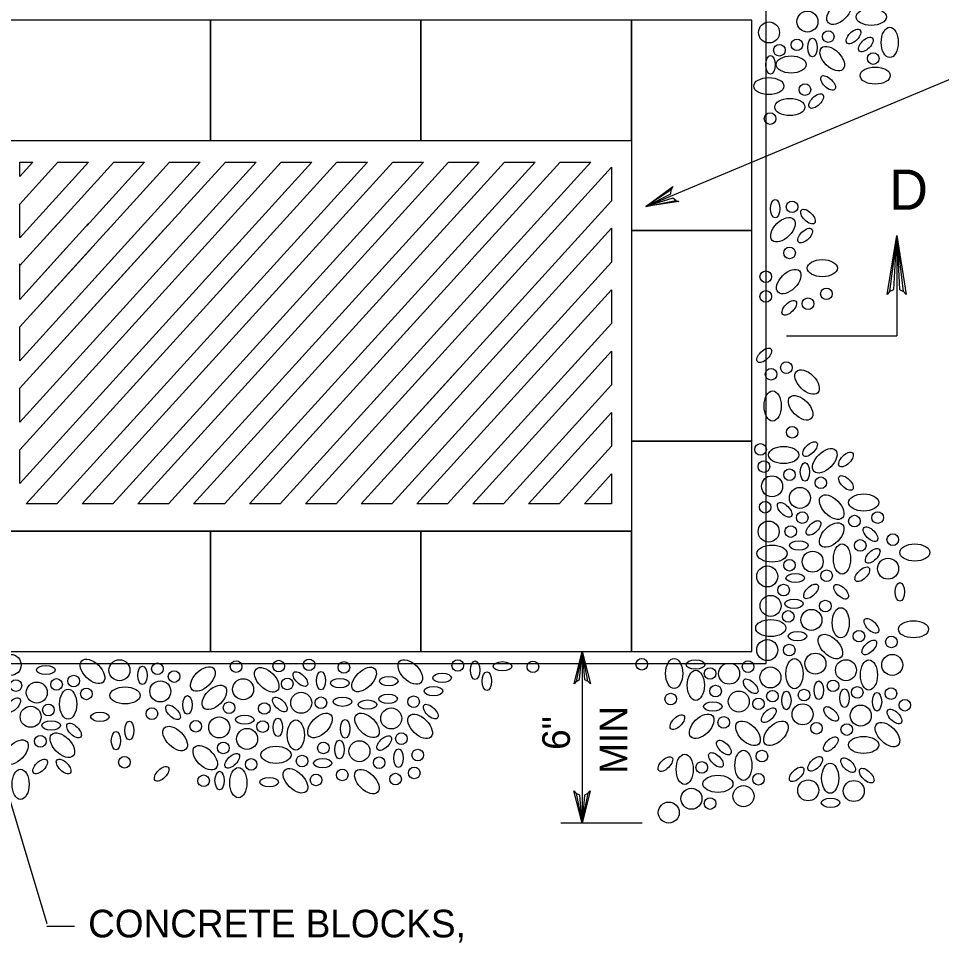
# Model space of a CAD drawing. Extents: x 636183 to 639890, y 299162 to 300538.
# Drawn here: x 637448.6 to 637548.8, y 300175.9 to 300276.1 of the extents above; entities that cross this region are included whole.
import ezdxf

# ---------------------------------------------------------------- set-up
doc = ezdxf.new("R2010")
doc.units = 0
doc.layers.add('Default', color=7, linetype='Continuous')

msp = doc.modelspace()

# ---------------------------------------------------------------- linework, layer by layer
at = {"layer": 'Default'}
for p, q in [((637516.68, 300255.74), (637562.35, 300274.87)), ((637531.92, 300241.7), (637543.9, 300241.7)), ((637446.59, 300220.51), (637515.11, 300220.51)), ((637446.59, 300220.51), (637515.11, 300220.51)), ((637440.72, 300214.38), (637451.66, 300177.93)), ((637516.28, 300188.83), (637507.46, 300188.83)), ((637454.66, 300177.6), (637451.66, 300177.6))]:
    msp.add_line(p, q, dxfattribs=at)
for points in [[(637432.27, 300206.15), (637529.74, 300206.15), (637529.74, 300277.69), (637432.27, 300277.69)], [(637469.43, 300275.96), (637446.59, 300275.96), (637446.59, 300262.88), (637469.43, 300262.88)], [(637492.27, 300275.96), (637469.43, 300275.96), (637469.43, 300262.88), (637492.27, 300262.88)], [(637515.11, 300275.96), (637492.27, 300275.96), (637492.27, 300262.88), (637515.11, 300262.88)], [(637515.11, 300275.96), (637515.11, 300253.12), (637528.18, 300253.12), (637528.18, 300275.96)], [(637515.11, 300253.12), (637515.11, 300230.28), (637528.18, 300230.28), (637528.18, 300253.12)], [(637515.11, 300230.28), (637515.11, 300207.44), (637528.18, 300207.44), (637528.18, 300230.28)], [(637469.43, 300220.51), (637446.59, 300220.51), (637446.59, 300207.44), (637469.43, 300207.44)], [(637492.27, 300220.51), (637469.43, 300220.51), (637469.43, 300207.44), (637492.27, 300207.44)], [(637515.11, 300220.51), (637492.27, 300220.51), (637492.27, 300207.44), (637515.11, 300207.44)]]:
    msp.add_lwpolyline(points, close=True, dxfattribs=at)
for points in [[(637446.59, 300220.51), (637446.59, 300262.88), (637515.11, 300262.88), (637515.11, 300220.51)], [(637446.59, 300220.51), (637446.59, 300262.88), (637515.11, 300262.88), (637515.11, 300220.51)], [(637448.73, 300229.34), (637477.1, 300260.53)], [(637448.73, 300255.97), (637452.87, 300260.53)], [(637448.73, 300225.68), (637480.43, 300260.53)], [(637448.73, 300232.34), (637474.37, 300260.53)], [(637448.73, 300252.31), (637456.2, 300260.53)], [(637448.73, 300258.97), (637450.14, 300260.53)], [(637448.73, 300258.97), (637448.73, 300260.53), (637450.14, 300260.53)], [(637448.73, 300229.34), (637477.1, 300260.53)], [(637448.73, 300255.97), (637452.87, 300260.53)], [(637448.73, 300225.68), (637480.43, 300260.53)], [(637448.73, 300232.34), (637474.37, 300260.53)], [(637448.73, 300252.31), (637456.2, 300260.53)], [(637448.73, 300258.97), (637450.14, 300260.53)], [(637448.73, 300258.97), (637448.73, 300260.53), (637450.14, 300260.53)], [(637449.44, 300223.46), (637483.15, 300260.53)], [(637449.44, 300223.46), (637483.15, 300260.53)], [(637452.52, 300253.48), (637458.93, 300260.53)], [(637452.52, 300253.48), (637458.93, 300260.53)], [(637452.77, 300223.46), (637486.48, 300260.53)], [(637452.77, 300223.46), (637486.48, 300260.53)], [(637452.87, 300260.53), (637456.2, 300260.53)], [(637452.87, 300260.53), (637456.2, 300260.53)], [(637455.49, 300223.46), (637489.21, 300260.53)], [(637455.49, 300223.46), (637489.21, 300260.53)], [(637455.99, 300253.64), (637462.26, 300260.53)], [(637455.99, 300253.64), (637462.26, 300260.53)], [(637458.21, 300253.08), (637464.98, 300260.53)], [(637458.21, 300253.08), (637464.98, 300260.53)], [(637458.82, 300223.46), (637492.54, 300260.53)], [(637458.82, 300223.46), (637492.54, 300260.53)], [(637458.93, 300260.53), (637462.26, 300260.53)], [(637458.93, 300260.53), (637462.26, 300260.53)], [(637461.55, 300223.46), (637495.26, 300260.53)], [(637461.55, 300223.46), (637495.26, 300260.53)], [(637464.72, 300256.58), (637468.31, 300260.53)], [(637464.72, 300256.58), (637468.31, 300260.53)], [(637464.88, 300223.46), (637498.59, 300260.53)], [(637464.88, 300223.46), (637498.59, 300260.53)], [(637464.98, 300260.53), (637468.31, 300260.53)], [(637464.98, 300260.53), (637468.31, 300260.53)], [(637466.15, 300255.15), (637471.04, 300260.53)], [(637466.15, 300255.15), (637471.04, 300260.53)], [(637467.6, 300223.46), (637501.32, 300260.53)], [(637467.6, 300223.46), (637501.32, 300260.53)], [(637470.94, 300223.46), (637504.65, 300260.53)], [(637470.94, 300223.46), (637504.65, 300260.53)], [(637471.04, 300260.53), (637474.37, 300260.53)], [(637471.04, 300260.53), (637474.37, 300260.53)], [(637476.99, 300223.46), (637510.71, 300260.53)], [(637476.99, 300223.46), (637510.71, 300260.53)], [(637477.1, 300260.53), (637480.43, 300260.53)], [(637477.1, 300260.53), (637480.43, 300260.53)], [(637479.72, 300223.46), (637512.96, 300260.01)], [(637479.72, 300223.46), (637512.96, 300260.01)], [(637483.15, 300260.53), (637486.48, 300260.53)], [(637483.15, 300260.53), (637486.48, 300260.53)], [(637489.21, 300260.53), (637492.54, 300260.53)], [(637489.21, 300260.53), (637492.54, 300260.53)], [(637495.26, 300260.53), (637498.59, 300260.53)], [(637495.26, 300260.53), (637498.59, 300260.53)], [(637497.44, 300249.61), (637507.38, 300260.53)], [(637497.44, 300249.61), (637507.38, 300260.53)], [(637501.32, 300260.53), (637504.65, 300260.53)], [(637501.32, 300260.53), (637504.65, 300260.53)], [(637507.38, 300260.53), (637510.71, 300260.53)], [(637507.38, 300260.53), (637510.71, 300260.53)], [(637512.96, 300260.01), (637512.96, 300256.35)], [(637512.96, 300260.01), (637512.96, 300256.35)], [(637519.92, 300256.37), (637520.25, 300256.26), (637516.68, 300255.74), (637519.92, 300256.37), (637519.6, 300256.64), (637516.68, 300255.74), (637519.4, 300257.12), (637519.42, 300257.54), (637516.68, 300255.74), (637519.59, 300257.88), (637519.42, 300257.54)], [(637448.73, 300239), (637464.76, 300256.63)], [(637448.73, 300252.31), (637448.73, 300255.97)], [(637448.73, 300252.31), (637448.73, 300255.97)], [(637502.14, 300244.45), (637512.96, 300256.35)], [(637502.14, 300244.45), (637512.96, 300256.35)], [(637448.73, 300236), (637466.32, 300255.34)], [(637448.73, 300245.65), (637456.2, 300253.87)], [(637448.73, 300249.32), (637452.74, 300253.73)], [(637448.73, 300242.66), (637458.47, 300253.36)], [(637448.73, 300236), (637464.36, 300253.19)], [(637448.73, 300239), (637461.52, 300253.06)], [(637485.77, 300223.46), (637512.96, 300253.36)], [(637485.77, 300223.46), (637512.96, 300253.36)], [(637512.96, 300253.36), (637512.96, 300249.69)], [(637512.96, 300253.36), (637512.96, 300249.69)], [(637543.13, 300246.49), (637543.57, 300246.71), (637543.9, 300252.59), (637543.13, 300246.49), (637542.86, 300246.17), (637543.9, 300252.59), (637544.19, 300246.72), (637544.62, 300246.5), (637543.9, 300252.59), (637544.92, 300246.17), (637544.62, 300246.5)], [(637543.9, 300252.59), (637543.9, 300241.7)], [(637448.73, 300249.32), (637450.51, 300251.27)], [(637448.73, 300242.66), (637456.54, 300251.25)], [(637448.73, 300245.65), (637453.74, 300251.17)], [(637473.66, 300223.46), (637497.65, 300249.83)], [(637489.1, 300223.46), (637512.96, 300249.69)], [(637489.1, 300223.46), (637512.96, 300249.69)], [(637448.73, 300245.65), (637448.73, 300249.51)], [(637448.73, 300245.65), (637448.73, 300249.51)], [(637491.83, 300223.46), (637512.96, 300246.7)], [(637491.83, 300223.46), (637512.96, 300246.7)], [(637512.96, 300246.7), (637512.96, 300243.03)], [(637512.96, 300246.7), (637512.96, 300243.03)], [(637483.05, 300223.46), (637502.26, 300244.58)], [(637448.73, 300239), (637448.73, 300242.66)], [(637448.73, 300239), (637448.73, 300242.66)], [(637473.66, 300223.46), (637491.8, 300243.4)], [(637495.16, 300223.46), (637512.96, 300243.03)], [(637495.16, 300223.46), (637512.96, 300243.03)], [(637497.89, 300223.46), (637512.96, 300240.04)], [(637497.89, 300223.46), (637512.96, 300240.04)], [(637512.96, 300240.04), (637512.96, 300236.38)], [(637512.96, 300240.04), (637512.96, 300236.38)], [(637483.05, 300223.46), (637496.34, 300238.08)], [(637448.73, 300232.34), (637448.73, 300236)], [(637448.73, 300232.34), (637448.73, 300236)], [(637501.22, 300223.46), (637512.96, 300236.38)], [(637501.22, 300223.46), (637512.96, 300236.38)], [(637503.94, 300223.46), (637512.96, 300233.38)], [(637503.94, 300223.46), (637512.96, 300233.38)], [(637512.96, 300233.38), (637512.96, 300229.72)], [(637512.96, 300233.38), (637512.96, 300229.72)], [(637507.27, 300223.46), (637512.96, 300229.72)], [(637507.27, 300223.46), (637512.96, 300229.72)], [(637448.73, 300225.68), (637448.73, 300229.34)], [(637448.73, 300225.68), (637448.73, 300229.34)], [(637510, 300223.46), (637512.96, 300226.72)], [(637512.96, 300226.72), (637512.96, 300223.46), (637510, 300223.46)], [(637510, 300223.46), (637512.96, 300226.72)], [(637512.96, 300226.72), (637512.96, 300223.46), (637510, 300223.46)], [(637452.77, 300223.46), (637449.44, 300223.46)], [(637452.77, 300223.46), (637449.44, 300223.46)], [(637458.82, 300223.46), (637455.49, 300223.46)], [(637458.82, 300223.46), (637455.49, 300223.46)], [(637464.88, 300223.46), (637461.55, 300223.46)], [(637464.88, 300223.46), (637461.55, 300223.46)], [(637470.94, 300223.46), (637467.6, 300223.46)], [(637470.94, 300223.46), (637467.6, 300223.46)], [(637476.99, 300223.46), (637473.66, 300223.46)], [(637476.99, 300223.46), (637473.66, 300223.46)], [(637483.05, 300223.46), (637479.72, 300223.46)], [(637483.05, 300223.46), (637479.72, 300223.46)], [(637489.1, 300223.46), (637485.77, 300223.46)], [(637489.1, 300223.46), (637485.77, 300223.46)], [(637495.16, 300223.46), (637491.83, 300223.46)], [(637495.16, 300223.46), (637491.83, 300223.46)], [(637501.22, 300223.46), (637497.89, 300223.46)], [(637501.22, 300223.46), (637497.89, 300223.46)], [(637507.27, 300223.46), (637503.94, 300223.46)], [(637507.27, 300223.46), (637503.94, 300223.46)], [(637509.12, 300204.2), (637508.9, 300203.93), (637509.76, 300207.44), (637509.12, 300204.2), (637509.49, 300204.4), (637509.76, 300207.44), (637510.02, 300204.41), (637510.39, 300204.22), (637509.76, 300207.44), (637510.65, 300203.94), (637510.39, 300204.22)], [(637509.76, 300207.44), (637509.76, 300188.83)], [(637510.4, 300192.07), (637510.62, 300192.34), (637509.76, 300188.83), (637510.4, 300192.07), (637510.02, 300191.87), (637509.76, 300188.83), (637509.5, 300191.86), (637509.12, 300192.05), (637509.76, 300188.83), (637508.87, 300192.33), (637509.12, 300192.05)]]:
    msp.add_lwpolyline(points, dxfattribs=at)
for centre, radius in [((637534.21, 300275.79), 1.14), ((637530.04, 300274.61), 1.14), ((637536.47, 300274.16), 0.63), ((637533.07, 300273.27), 0.63), ((637531.16, 300272.68), 0.63), ((637541.35, 300271.78), 0.63), ((637533.94, 300268.41), 0.63), ((637530.16, 300265.26), 0.63), ((637532.54, 300255.69), 0.63), ((637532.27, 300250.69), 0.63), ((637529.69, 300248.11), 0.63), ((637529.69, 300245.97), 0.63), ((637536.27, 300246.25), 0.63), ((637534.27, 300245.18), 0.63), ((637531.92, 300238.24), 0.63), ((637530.26, 300237.52), 0.63), ((637532.55, 300231.23), 0.63), ((637529.12, 300229.37), 0.63), ((637529.49, 300227.51), 0.63), ((637532.26, 300226.63), 0.63), ((637530.37, 300225.37), 1.14), ((637535.66, 300225.75), 0.63), ((637533.39, 300224.11), 1.14), ((637529.62, 300223.1), 0.63), ((637533.65, 300221.97), 0.63), ((637541.83, 300221.97), 0.63), ((637530, 300220.46), 1.14), ((637539.31, 300221.59), 0.63), ((637532.39, 300220.46), 0.63), ((637539.94, 300218.95), 0.63), ((637543.47, 300219.58), 0.63), ((637534.78, 300217.19), 1.14), ((637542.96, 300216.43), 1.14), ((637529.85, 300215.59), 1.14), ((637532.26, 300216.81), 0.63), ((637536.29, 300215.67), 0.63), ((637531.62, 300214.11), 0.63), ((637530.21, 300212.4), 1.14), ((637536.15, 300212.38), 0.63), ((637532.12, 300211.25), 0.63), ((637534.64, 300210.87), 1.14), ((637539.8, 300209.11), 0.63), ((637529.85, 300207.6), 1.14), ((637543.32, 300208.48), 0.63), ((637532.24, 300207.6), 0.63), ((637447.74, 300205.99), 1.14), ((637459.55, 300205.41), 1.14), ((637476.83, 300205.86), 0.63), ((637480.12, 300206), 0.63), ((637496.26, 300205.93), 0.63), ((637516.23, 300206.06), 0.63), ((637535.07, 300206.13), 1.14), ((637538.39, 300205.42), 1.14), ((637543.41, 300205.99), 1.14), ((637463.67, 300205.57), 0.63), ((637472.21, 300205.81), 0.63), ((637483.91, 300205.72), 0.63), ((637504.42, 300205.78), 0.63), ((637523.64, 300205.06), 0.63), ((637525.71, 300205.04), 1.14), ((637527.76, 300205.8), 0.63), ((637530.19, 300204.63), 1.14), ((637452.72, 300203.87), 0.63), ((637454.58, 300204.24), 0.63), ((637465.48, 300204.73), 0.63), ((637472.97, 300203.35), 1.14), ((637477.76, 300203.93), 0.63), ((637448.31, 300203.75), 0.63), ((637450.58, 300202.99), 1.14), ((637455.96, 300202.85), 0.63), ((637463.98, 300203.12), 1.14), ((637524.24, 300203.15), 0.63), ((637536.99, 300203.72), 0.63), ((637539.62, 300203.01), 0.63), ((637543.27, 300202.88), 0.63), ((637479.27, 300201.88), 1.14), ((637481.41, 300201.88), 0.63), ((637491.47, 300202), 0.63), ((637519.37, 300202.29), 0.63), ((637526.76, 300202.02), 1.14), ((637530.41, 300202.6), 0.63), ((637533.84, 300202.72), 0.63), ((637449.91, 300200.36), 1.14), ((637451.84, 300201.1), 0.63), ((637471.44, 300201.35), 0.63), ((637475.27, 300201.26), 0.63), ((637528.9, 300201.77), 0.63), ((637533.68, 300200.63), 1.14), ((637539.99, 300200.49), 1.14), ((637544.78, 300201.62), 0.63), ((637463.07, 300200.7), 0.63), ((637489.04, 300200.18), 1.14), ((637467.83, 300199.33), 0.63), ((637470.37, 300199.21), 1.14), ((637475.09, 300199.3), 0.63), ((637525.12, 300199.75), 0.63), ((637535.19, 300199.12), 0.63), ((637538.48, 300198.98), 0.63), ((637473.4, 300197.96), 1.14), ((637490.14, 300197.99), 0.63), ((637450.96, 300197.7), 0.63), ((637470.82, 300196.98), 0.63), ((637481.68, 300196.98), 0.63), ((637485.59, 300196.63), 1.14), ((637491.92, 300196.21), 0.63), ((637529.27, 300196.1), 0.63), ((637460.09, 300195.43), 0.63), ((637473.84, 300195.2), 0.63), ((637479.36, 300195.56), 0.63), ((637487.73, 300195.38), 0.63), ((637522.74, 300194.87), 0.63), ((637483.73, 300194.05), 0.63), ((637491.54, 300194.27), 0.63), ((637468.68, 300193.42), 0.63), ((637480.88, 300193.51), 0.63), ((637489.51, 300193.6), 0.63), ((637528.9, 300193.58), 0.63), ((637534.29, 300192.38), 1.14), ((637539.24, 300192.31), 1.14), ((637521.62, 300191.47), 1.14), ((637527.27, 300191.75), 1.14), ((637523.64, 300190.95), 0.63), ((637519.16, 300189.97), 1.14)]:
    msp.add_circle(centre, radius, dxfattribs=at)
for centre, major_axis, ratio in [((637537.65, 300276.8), (1.16, 1.16), 0.565936), ((637541.13, 300276.3), (1.64, 0), 0.565936), ((637539.21, 300274.17), (0.712, 0.712), 0.5), ((637543.14, 300273.53), (0, -1.64), 0.565936), ((637534.75, 300272.98), (0, -1.01), 0.5), ((637540.55, 300273.31), (0.712, 0.712), 0.5), ((637536.9, 300271.77), (1.16, -1.16), 0.565936), ((637530.2, 300271.1), (0, 1.01), 0.5), ((637532.44, 300271.13), (1.64, 0), 0.565936), ((637541.56, 300269.93), (1.64, 0), 0.565936), ((637530.02, 300268.79), (1.64, 0), 0.565936), ((637536.45, 300269.13), (0.712, -0.712), 0.5), ((637535.16, 300267.17), (0.712, 0.712), 0.5), ((637532.3, 300266.52), (1.64, 0), 0.565936), ((637530.71, 300255.49), (0, 1.01), 0.5), ((637531.55, 300253.21), (1.16, 1.16), 0.565936), ((637534.27, 300254.63), (0.712, -0.712), 0.5), ((637533.96, 300252.57), (0.712, 0.712), 0.5), ((637535.82, 300249.04), (1.64, 0), 0.565936), ((637532.18, 300247.58), (1.16, 1.16), 0.565936), ((637532.24, 300244.74), (0.712, 0.712), 0.5), ((637529.52, 300239.58), (0.712, 0.712), 0.5), ((637534.17, 300236.68), (1.16, -1.16), 0.565936), ((637530.43, 300234.09), (0, -1.64), 0.565936), ((637533.47, 300233.88), (1.16, -1.16), 0.565936), ((637531.63, 300228.77), (1.64, 0), 0.565936), ((637534.49, 300229.41), (0.712, 0.712), 0.5), ((637536.09, 300228.14), (1.16, 1.16), 0.565936), ((637538.39, 300228.28), (0.712, 0.712), 0.5), ((637533.94, 300226.93), (0, 1.01), 0.5), ((637538.39, 300225.73), (0.712, -0.712), 0.5), ((637536.84, 300223.11), (1.16, -1.16), 0.565936), ((637540.32, 300223.61), (1.64, 0), 0.565936), ((637531.74, 300222.81), (-0.712, 0.712), 0.5), ((637534.87, 300220.85), (0.712, 0.712), 0.5), ((637536.84, 300220.08), (1.16, 1.16), 0.565936), ((637541.06, 300220.17), (-0.712, 0.712), 0.5), ((637530.37, 300218.07), (1.64, 0), 0.565936), ((637533.27, 300218.95), (-1.01, 0), 0.5), ((637537.96, 300217.49), (0, -1.64), 0.565936), ((637541.29, 300217.83), (0.712, 0.712), 0.5), ((637545.86, 300218.19), (1.64, 0), 0.565936), ((637540.16, 300215.82), (0.712, 0.712), 0.5), ((637532.89, 300215.42), (-1.01, 0), 0.5), ((637534.6, 300213.97), (-0.712, -0.712), 0.5), ((637537.87, 300213.93), (0.712, -0.712), 0.5), ((637544.24, 300213.91), (0, 1.01), 0.5), ((637532.75, 300212.63), (-1.01, 0), 0.5), ((637537.82, 300210.56), (0, 1.64), 0.565936), ((637530.23, 300209.99), (1.64, 0), 0.565936), ((637541.15, 300210.23), (0.712, -0.712), 0.5), ((637545.72, 300209.86), (1.64, 0), 0.565936), ((637533.13, 300209.11), (-1.01, 0), 0.5), ((637536.7, 300207.98), (1.16, -1.16), 0.565936), ((637540.92, 300207.89), (-0.712, -0.712), 0.5), ((637456.62, 300205.29), (1.16, -1.16), 0.565936), ((637491.11, 300205.22), (1.16, -1.16), 0.565936), ((637519.75, 300205.06), (0, -1.64), 0.565936), ((637522.06, 300206.03), (1.01, 0), 0.5), ((637532.8, 300205.04), (0, -1.64), 0.565936), ((637540.88, 300204.9), (0, -1.64), 0.565936), ((637451.56, 300205.44), (1.01, 0), 0.5), ((637462.04, 300204.86), (0, -1.01), 0.5), ((637468.6, 300204.46), (-1.16, -1.16), 0.565936), ((637475.53, 300204.37), (1.16, -1.16), 0.565936), ((637486.1, 300204.41), (-1.16, -1.16), 0.565936), ((637498.14, 300205.41), (0, -1.01), 0.5), ((637501.12, 300205.84), (-1.01, 0), 0.5), ((637479.18, 300204.46), (-0.712, 0.712), 0.5), ((637481.42, 300204.28), (0, 1.01), 0.5), ((637483.47, 300204.02), (1.01, 0), 0.5), ((637488.77, 300204.23), (1.01, 0), 0.5), ((637494.56, 300204.58), (1.01, 0), 0.5), ((637499.42, 300204.23), (0, -1.01), 0.5), ((637522.1, 300203.78), (0, -1.64), 0.565936), ((637528.05, 300203.67), (-0.712, 0.712), 0.5), ((637460.16, 300202.68), (1.64, 0), 0.565936), ((637469.85, 300202.47), (-1.16, -1.16), 0.565936), ((637493.63, 300203.15), (1.01, 0), 0.5), ((637535.44, 300203.24), (0, 1.01), 0.5), ((637448.02, 300201.62), (0.712, 0.712), 0.5), ((637453.98, 300201.73), (0, -1.64), 0.565936), ((637466.92, 300201.65), (0, -1.01), 0.5), ((637476.96, 300201.7), (-0.712, 0.712), 0.5), ((637483.76, 300202), (1.01, 0), 0.5), ((637488.7, 300202.3), (1.01, 0), 0.5), ((637531.92, 300202.14), (0, 1.01), 0.5), ((637538.23, 300202.38), (0, 1.01), 0.5), ((637541.76, 300202), (0, 1.01), 0.5), ((637465.36, 300200.85), (-0.712, 0.712), 0.5), ((637486.47, 300201.68), (1.01, 0), 0.5), ((637493.33, 300200.92), (-0.712, 0.712), 0.5), ((637523.94, 300201.48), (-1.01, 0), 0.5), ((637530.01, 300200.54), (-0.712, -0.712), 0.5), ((637536.78, 300200.67), (-0.712, 0.712), 0.5), ((637457.43, 300200.36), (1.01, 0), 0.5), ((637473.14, 300200.05), (-1.01, 0), 0.5), ((637481.31, 300199.42), (1.16, 1.16), 0.565936), ((637486.42, 300199.43), (1.16, -1.16), 0.565936), ((637492.18, 300199.32), (1.16, -1.16), 0.565936), ((637520.09, 300199.78), (-0.712, -0.712), 0.5), ((637522.73, 300199.33), (-1.16, -1.16), 0.565936), ((637543.66, 300200.4), (0.712, -0.712), 0.5), ((637452.14, 300199.43), (1.01, 0), 0.5), ((637454.62, 300198.87), (0.712, -0.712), 0.5), ((637460.62, 300198.87), (0, -1.01), 0.5), ((637465.59, 300198), (1.16, -1.16), 0.565936), ((637476.74, 300199.22), (0, -1.01), 0.5), ((637478.69, 300198.38), (0, -1.64), 0.565936), ((637484.04, 300199.05), (0, -1.01), 0.5), ((637527.76, 300198.57), (1.16, -1.16), 0.565936), ((637530.79, 300198.57), (-1.16, -1.16), 0.565936), ((637542.89, 300198.43), (1.16, -1.16), 0.565936), ((637453.35, 300197.28), (1.16, -1.16), 0.565936), ((637459.17, 300197.77), (0, -1.01), 0.5), ((637448.32, 300196.52), (-1.16, -1.16), 0.565936), ((637483.42, 300196.82), (0, -1.01), 0.5), ((637488.28, 300197.51), (-0.712, -0.712), 0.5), ((637525.14, 300197.02), (0.712, -0.712), 0.5), ((637536.74, 300197.4), (-0.712, -0.712), 0.5), ((637540.3, 300197.31), (-1.64, 0), 0.565936), ((637468.86, 300195.92), (1.16, -1.16), 0.565936), ((637471.79, 300195.59), (-0.712, -0.712), 0.5), ((637476.54, 300196.24), (1.64, 0), 0.565936), ((637489.83, 300195.87), (0, 1.01), 0.5), ((637524.28, 300195.68), (0.712, -0.712), 0.5), ((637527.26, 300195.09), (0, -1.64), 0.565936), ((637450.94, 300194.97), (-0.712, -0.712), 0.5), ((637453.49, 300194.97), (0.712, -0.712), 0.5), ((637481.6, 300195.33), (-1.01, 0), 0.5), ((637518.79, 300195.23), (-0.712, -0.712), 0.5), ((637520.89, 300194.66), (0, -1.64), 0.565936), ((637535.05, 300195.26), (-0.712, -0.712), 0.5), ((637538.63, 300195.11), (0.712, -0.712), 0.5), ((637448.82, 300193.04), (0, -1.64), 0.565936), ((637464.13, 300194.17), (-0.712, -0.712), 0.5), ((637470.42, 300193.44), (0, -1.01), 0.5), ((637472.45, 300193.21), (0, -1.64), 0.565936), ((637478.65, 300193.42), (1.16, -1.16), 0.565936), ((637486.4, 300193.33), (1.16, -1.16), 0.565936), ((637533.04, 300194.12), (-0.712, -0.712), 0.5), ((637536.68, 300193.7), (0, -1.64), 0.565936), ((637540.64, 300193.98), (0.712, -0.712), 0.5), ((637475.79, 300193.28), (1.01, 0), 0.5), ((637524.49, 300193.09), (-1.64, 0), 0.565936), ((637536.72, 300191.03), (1.01, 0), 0.5)]:
    msp.add_ellipse(centre, major_axis=major_axis, ratio=ratio, start_param=0, end_param=6.283175, dxfattribs=at)

# ---------------------------------------------------------------- texts
for s, height, p in [('D', 4.37, (637543.07, 300255.37)), ('CONCRETE BLOCKS,', 2.998, (637456.15, 300176.43))]:
    msp.add_text(s, height=height, dxfattribs=at).set_placement(p)
for s, p in [('MIN', (637514.65, 300194.17)), ('6"', (637508.43, 300196.77))]:
    msp.add_text(s, height=2.998, rotation=90, dxfattribs=at).set_placement(p)

doc.saveas('drawing.dxf')
